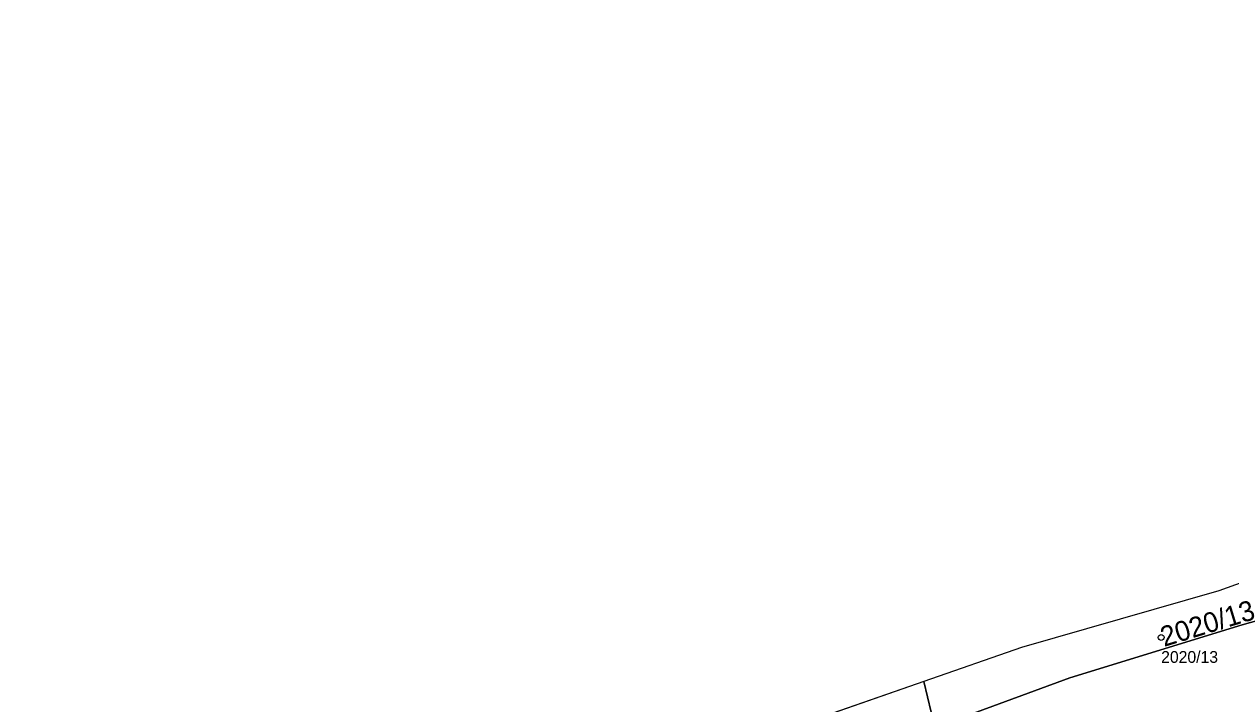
# Model space of a CAD drawing. Extents: x -762274 to -759271, y -1061928 to -1059060.
# Drawn here: x -761526.6 to -761424.1, y -1060184.6 to -1060126.9 of the extents above; entities that cross this region are included whole.
import ezdxf

# ---------------------------------------------------------------- set-up
doc = ezdxf.new("R2010")
doc.units = 0
for name, color, linetype in [('Definiční body', 7, 'Continuous'), ('Hranice parcel', 7, 'Continuous'), ('Parcelní čísla', 7, 'Continuous'), ('Polygon ku', 7, 'Continuous'), ('Polygon parcely', 7, 'Continuous')]:
    doc.layers.add(name, color=color, linetype=linetype)

msp = doc.modelspace()

# ---------------------------------------------------------------- linework, layer by layer
at = {"layer": 'Definiční body'}
msp.add_circle((-761429.99, -1060178.96), 0.25, dxfattribs=at)
at = {"layer": 'Hranice parcel'}
for p, q in [((-761450.15, -1060182.7), (-761468.39, -1060189.05)), ((-761449.23, -1060186.62), (-761450.15, -1060182.7))]:
    msp.add_line(p, q, dxfattribs=at)
for points in [[(-761405.05, -1060167.79), (-761406.85, -1060168.43), (-761425.1, -1060174.99), (-761441.85, -1060179.81), (-761450.15, -1060182.7)], [(-761404.43, -1060172.49), (-761406.61, -1060173.28), (-761423.1, -1060177.89), (-761437.76, -1060182.39), (-761449.23, -1060186.62)]]:
    msp.add_lwpolyline(points, dxfattribs=at)
at = {"layer": 'Polygon ku'}
msp.add_lwpolyline([(-761339.67, -1060110.2), (-761317.92, -1060131.55), (-761315.85, -1060136.42), (-761314.24, -1060138.46), (-761312.39, -1060140.8), (-761337.47, -1060149), (-761354.48, -1060152.45), (-761364.74, -1060154.59), (-761375.49, -1060157.33), (-761381.11, -1060159.32), (-761405.05, -1060167.79), (-761406.85, -1060168.43), (-761425.1, -1060174.99), (-761441.85, -1060179.81), (-761450.15, -1060182.7), (-761468.39, -1060189.05), (-761472.82, -1060190.59), (-761481.76, -1060193.77), (-761497.29, -1060196.47), (-761503.92, -1060197.62), (-761521.42, -1060199.01), (-761527.33, -1060199.48)], dxfattribs=at)
at = {"layer": 'Polygon parcely'}
for points in [[(-761406.85, -1060168.43), (-761425.1, -1060174.99), (-761441.85, -1060179.81), (-761450.15, -1060182.7), (-761449.23, -1060186.62), (-761437.76, -1060182.39), (-761423.1, -1060177.89), (-761406.61, -1060173.28), (-761404.43, -1060172.49), (-761405.05, -1060167.79)], [(-761417.18, -1060230.93), (-761397.38, -1060225.58), (-761404.43, -1060172.49), (-761406.61, -1060173.28), (-761423.1, -1060177.89), (-761437.76, -1060182.39), (-761449.23, -1060186.62), (-761436.36, -1060241.66)], [(-761450.15, -1060182.7), (-761468.39, -1060189.05), (-761467.39, -1060193.32), (-761449.23, -1060186.62)]]:
    msp.add_lwpolyline(points, close=True, dxfattribs=at)

# ---------------------------------------------------------------- texts
at = {"layer": 'Definiční body'}
msp.add_text('2020/13', height=1, dxfattribs=at).set_placement((-761429.99, -1060181.12))
at = {"layer": 'Parcelní čísla'}
msp.add_text('2020/13', height=1.7, rotation=17, dxfattribs=at).set_placement((-761429.74, -1060179.77))

doc.saveas('drawing.dxf')
